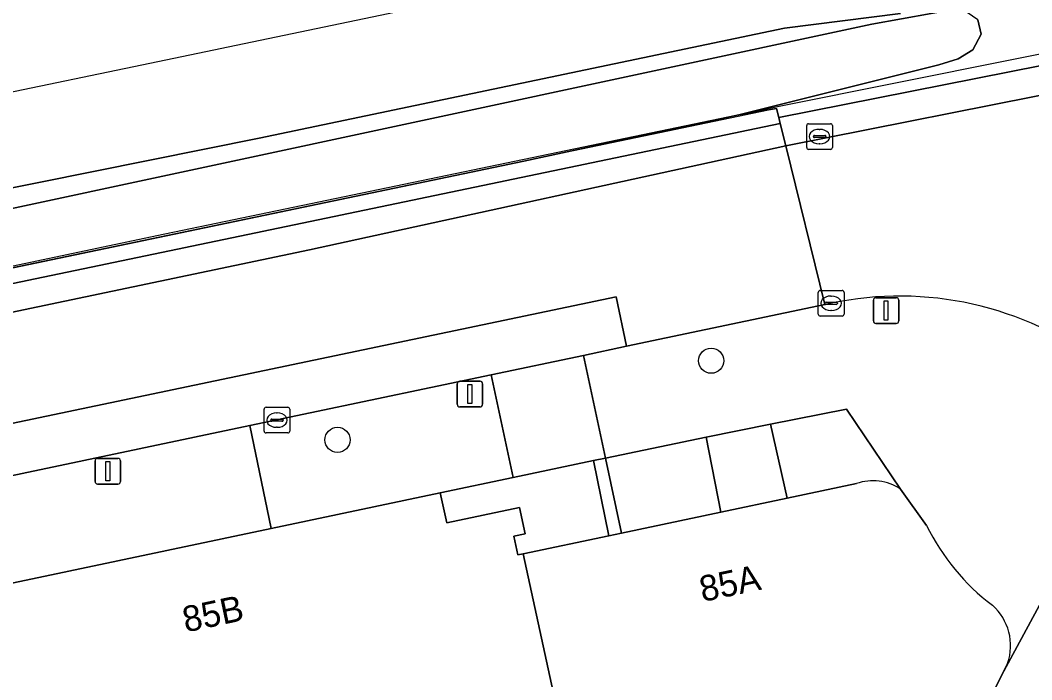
# Model space of a CAD drawing. Extents: x 162989 to 165008, y 383432 to 384338.
# Drawn here: x 163801.29 to 163840.69, y 384103.71 to 384129.41 of the extents above; entities that cross this region are included whole.
import ezdxf

# ---------------------------------------------------------------- set-up
doc = ezdxf.new("R2010")
doc.units = 0
for name, color, linetype in [('IMGEO_Boom', 7, 'Continuous'), ('IMGEO_Grasland_overig', 7, 'Continuous'), ('IMGEO_Greppel_droge_sloot', 7, 'Continuous'), ('IMGEO_Groenvoorziening', 7, 'Continuous'), ('IMGEO_Haag', 7, 'Continuous'), ('IMGEO_Hek', 7, 'Continuous'), ('IMGEO_Kolk', 7, 'Continuous'), ('IMGEO_Lichtmast', 7, 'Continuous'), ('IMGEO_Pand', 7, 'Continuous'), ('IMGEO_Pand_nummerreeks', 7, 'Continuous'), ('IMGEO_Parkeervlak_gesloten', 7, 'Continuous'), ('IMGEO_Rijbaan_lokaal_gesloten', 7, 'Continuous'), ('IMGEO_Rijbaan_lokaal_open', 7, 'Continuous'), ('IMGEO_Spoor', 7, 'Continuous'), ('IMGEO_Spoorbaan_halfverhard', 7, 'Continuous'), ('IMGEO_Voetpad_open', 7, 'Continuous')]:
    doc.layers.add(name, color=color, linetype=linetype)

msp = doc.modelspace()

# ---------------------------------------------------------------- linework, layer by layer
at = {"layer": 'IMGEO_Boom'}
for centre in [(163828.202, 384116.141), (163813.649, 384113.057)]:
    msp.add_circle(centre, 0.489, dxfattribs=at)
at = {"layer": 'IMGEO_Grasland_overig'}
for points in [[(163838.592, 384129.42), (163838.715, 384128.865), (163838.4, 384128.258), (163837.828, 384127.908), (163837.073, 384127.674), (163829.276, 384125.722), (163830.751, 384125.97), (163830.839, 384125.616), (163846.249, 384128.665), (163846.224, 384128.913), (163855.457, 384130.728)], [(163764.809, 384114.316), (163834.463, 384129.25), (163837.931, 384129.88)], [(163835.571, 384129.666), (163831.06, 384129.095), (163810.596, 384124.813), (163789.104, 384120.481)]]:
    msp.add_lwpolyline(points, dxfattribs=at)
at = {"layer": 'IMGEO_Greppel_droge_sloot'}
msp.add_lwpolyline([(163651.615, 384088.607), (163721.236, 384103.128), (163796.575, 384118.842), (163820.911, 384123.918), (163829.276, 384125.722), (163837.073, 384127.674), (163837.828, 384127.908), (163838.4, 384128.258), (163838.715, 384128.865), (163838.592, 384129.42), (163837.931, 384129.88), (163834.463, 384129.25), (163764.809, 384114.316), (163747.271, 384110.947), (163722.892, 384105.78), (163713.242, 384103.924), (163695.738, 384099.89)], dxfattribs=at)
at = {"layer": 'IMGEO_Groenvoorziening'}
for points in [[(163651.736, 384088.019), (163830.895, 384125.387), (163830.839, 384125.616), (163830.751, 384125.97), (163829.276, 384125.722), (163820.911, 384123.918), (163796.575, 384118.842), (163721.236, 384103.128), (163651.615, 384088.607)], [(163682.411, 384093.294), (163707.965, 384098.574), (163724.745, 384102.036), (163812.556, 384120.462), (163831.109, 384124.518), (163830.895, 384125.387), (163651.736, 384088.019)]]:
    msp.add_lwpolyline(points, dxfattribs=at)
at = {"layer": 'IMGEO_Haag'}
msp.add_lwpolyline([(163651.736, 384088.019), (163830.895, 384125.387), (163830.839, 384125.616), (163830.751, 384125.97), (163829.276, 384125.722), (163820.911, 384123.918), (163796.575, 384118.842), (163721.236, 384103.128), (163651.615, 384088.607)], dxfattribs=at)
at = {"layer": 'IMGEO_Hek'}
for points in [[(163774.371, 384114.211), (163806.617, 384121.018), (163830.855, 384126.062), (163844.511, 384128.802), (163854.414, 384130.95), (163855.366, 384133.259)], [(163830.751, 384125.97), (163651.615, 384088.607), (163494.89, 384056.228), (163459.651, 384049.074)]]:
    msp.add_lwpolyline(points, dxfattribs=at)
at = {"layer": 'IMGEO_Kolk'}
for p, q in [((163831.924, 384124.449), (163831.924, 384125.301)), ((163831.999, 384125.375), (163832.851, 384125.375)), ((163832.412, 384125.155), (163832.437, 384125.155)), ((163832.925, 384125.301), (163832.925, 384124.449)), ((163832.183, 384124.869), (163832.183, 384124.881)), ((163832.621, 384124.832), (163832.223, 384124.832)), ((163832.226, 384124.918), (163832.624, 384124.918)), ((163832.667, 384124.881), (163832.667, 384124.869)), ((163832.851, 384124.375), (163831.999, 384124.375)), ((163832.435, 384124.595), (163832.41, 384124.595)), ((163832.375, 384117.953), (163832.375, 384118.805)), ((163832.45, 384118.879), (163833.302, 384118.879)), ((163833.376, 384118.805), (163833.376, 384117.953)), ((163832.677, 384118.422), (163833.075, 384118.422)), ((163832.863, 384118.659), (163832.888, 384118.659)), ((163832.634, 384118.373), (163832.634, 384118.385)), ((163833.072, 384118.336), (163832.674, 384118.336)), ((163832.886, 384118.099), (163832.861, 384118.099)), ((163833.118, 384118.385), (163833.118, 384118.373)), ((163833.302, 384117.879), (163832.45, 384117.879)), ((163810.79, 384113.4), (163810.79, 384114.252)), ((163810.865, 384114.326), (163811.717, 384114.326)), ((163811.278, 384114.106), (163811.303, 384114.106)), ((163811.791, 384114.252), (163811.791, 384113.4)), ((163811.049, 384113.82), (163811.049, 384113.832)), ((163811.487, 384113.783), (163811.089, 384113.783)), ((163811.092, 384113.869), (163811.49, 384113.869)), ((163811.533, 384113.832), (163811.533, 384113.82)), ((163811.717, 384113.326), (163810.865, 384113.326)), ((163811.301, 384113.546), (163811.276, 384113.546))]:
    msp.add_line(p, q, dxfattribs=at)
for points in [[(163831.924, 384124.449), (163831.924, 384125.301)], [(163831.999, 384125.375), (163832.851, 384125.375)], [(163832.925, 384125.301), (163832.925, 384124.449)], [(163832.851, 384124.375), (163831.999, 384124.375)], [(163832.375, 384117.953), (163832.375, 384118.805)], [(163832.45, 384118.879), (163833.302, 384118.879)], [(163833.376, 384118.805), (163833.376, 384117.953)], [(163833.302, 384117.879), (163832.45, 384117.879)], [(163810.79, 384113.4), (163810.79, 384114.252)], [(163810.865, 384114.326), (163811.717, 384114.326)], [(163811.791, 384114.252), (163811.791, 384113.4)], [(163811.717, 384113.326), (163810.865, 384113.326)]]:
    msp.add_lwpolyline(points, dxfattribs=at)
for centre, radius, start, end in [((163832.001, 384125.299), 0.0765, 91.552, 178.448), ((163832.001, 384125.299), 0.0765, 91.552, 178.448), ((163832.849, 384125.299), 0.0765, 1.552, 88.448), ((163832.849, 384125.299), 0.0765, 1.552, 88.448), ((163832.223, 384124.878), 0.0403, 85.8775, 175.7526), ((163832.22, 384124.868), 0.0366, 178.938, 274.7102), ((163832.624, 384124.875), 0.043, 264.8664, 352.4533), ((163832.628, 384124.88), 0.0386, 1.7309, 96.639), ((163832.001, 384124.451), 0.0765, 181.552, 268.448), ((163832.001, 384124.451), 0.0765, 181.552, 268.448), ((163832.849, 384124.451), 0.0765, 271.552, 358.448), ((163832.849, 384124.451), 0.0765, 271.552, 358.448), ((163832.452, 384118.803), 0.0765, 91.552, 178.448), ((163832.452, 384118.803), 0.0765, 91.552, 178.448), ((163833.3, 384118.803), 0.0765, 1.552, 88.448), ((163833.3, 384118.803), 0.0765, 1.552, 88.448), ((163832.674, 384118.382), 0.0403, 85.8775, 175.7526), ((163833.079, 384118.384), 0.0386, 1.7309, 96.639), ((163832.671, 384118.372), 0.0366, 178.938, 274.7102), ((163833.075, 384118.379), 0.043, 264.8664, 352.4533), ((163832.452, 384117.955), 0.0765, 181.552, 268.448), ((163832.452, 384117.955), 0.0765, 181.552, 268.448), ((163833.3, 384117.955), 0.0765, 271.552, 358.448), ((163833.3, 384117.955), 0.0765, 271.552, 358.448), ((163810.867, 384114.25), 0.0765, 91.552, 178.448), ((163810.867, 384114.25), 0.0765, 91.552, 178.448), ((163811.715, 384114.25), 0.0765, 1.552, 88.448), ((163811.715, 384114.25), 0.0765, 1.552, 88.448), ((163811.089, 384113.829), 0.0403, 85.8775, 175.7526), ((163811.086, 384113.819), 0.0366, 178.938, 274.7102), ((163811.49, 384113.826), 0.043, 264.8664, 352.4533), ((163811.494, 384113.831), 0.0386, 1.7309, 96.639), ((163810.867, 384113.402), 0.0765, 181.552, 268.448), ((163810.867, 384113.402), 0.0765, 181.552, 268.448), ((163811.715, 384113.402), 0.0765, 271.552, 358.448), ((163811.715, 384113.402), 0.0765, 271.552, 358.448)]:
    msp.add_arc(centre, radius, start, end, dxfattribs=at)
for centre, major_axis, ratio, start_param, end_param in [((163832.411, 384124.875), (-0.387, 0.002), 0.722429, 4.712389, 7.853982), ((163832.436, 384124.875), (-0.39, 0.002), 0.717154, 1.570796, 4.712389), ((163832.862, 384118.379), (-0.387, 0.002), 0.722429, 4.712389, 7.853982), ((163832.887, 384118.379), (-0.39, 0.002), 0.717154, 1.570796, 4.712389), ((163811.277, 384113.826), (-0.387, 0.002), 0.722429, 4.712389, 7.853982), ((163811.302, 384113.826), (-0.39, 0.002), 0.717154, 1.570796, 4.712389)]:
    msp.add_ellipse(centre, major_axis=major_axis, ratio=ratio, start_param=start_param, end_param=end_param, dxfattribs=at)
at = {"layer": 'IMGEO_Lichtmast'}
for p, q in [((163834.519, 384117.694), (163834.519, 384118.494)), ((163834.519, 384118.494), (163834.519, 384117.694)), ((163834.619, 384118.594), (163835.409, 384118.594)), ((163835.409, 384118.594), (163834.619, 384118.594)), ((163835.509, 384118.494), (163835.509, 384117.694)), ((163835.509, 384117.694), (163835.509, 384118.494)), ((163835.409, 384117.594), (163834.619, 384117.594)), ((163834.619, 384117.594), (163835.409, 384117.594)), ((163818.409, 384115.343), (163819.199, 384115.343)), ((163819.199, 384115.343), (163818.409, 384115.343)), ((163818.309, 384114.443), (163818.309, 384115.243)), ((163818.309, 384115.243), (163818.309, 384114.443)), ((163819.299, 384115.243), (163819.299, 384114.443)), ((163819.299, 384114.443), (163819.299, 384115.243)), ((163819.199, 384114.343), (163818.409, 384114.343)), ((163818.409, 384114.343), (163819.199, 384114.343)), ((163804.206, 384111.436), (163804.206, 384112.236)), ((163804.206, 384112.236), (163804.206, 384111.436)), ((163804.306, 384112.336), (163805.096, 384112.336)), ((163805.096, 384112.336), (163804.306, 384112.336)), ((163805.196, 384112.236), (163805.196, 384111.436)), ((163805.196, 384111.436), (163805.196, 384112.236)), ((163805.096, 384111.336), (163804.306, 384111.336)), ((163804.306, 384111.336), (163805.096, 384111.336))]:
    msp.add_line(p, q, dxfattribs=at)
for points in [[(163834.939, 384118.469), (163835.089, 384118.469), (163835.089, 384117.719), (163834.939, 384117.719), (163834.939, 384118.469)], [(163818.729, 384115.218), (163818.879, 384115.218), (163818.879, 384114.468), (163818.729, 384114.468), (163818.729, 384115.218)], [(163804.626, 384112.211), (163804.776, 384112.211), (163804.776, 384111.461), (163804.626, 384111.461), (163804.626, 384112.211)]]:
    msp.add_lwpolyline(points, dxfattribs=at)
for centre, start, end in [((163834.619, 384118.494), 90, 180), ((163834.619, 384118.494), 90, 180), ((163835.409, 384118.494), 0, 90), ((163835.409, 384118.494), 360, 90), ((163834.619, 384117.694), 180, 270), ((163834.619, 384117.694), 180, 270), ((163835.409, 384117.694), 270, 0), ((163835.409, 384117.694), 270, 0), ((163818.409, 384115.243), 90, 180), ((163818.409, 384115.243), 90, 180), ((163819.199, 384115.243), 0, 90), ((163819.199, 384115.243), 360, 90), ((163818.409, 384114.443), 180, 270), ((163818.409, 384114.443), 180, 270), ((163819.199, 384114.443), 270, 0), ((163819.199, 384114.443), 270, 0), ((163804.306, 384112.236), 90, 180), ((163804.306, 384112.236), 90, 180), ((163805.096, 384112.236), 0, 90), ((163805.096, 384112.236), 360, 90), ((163804.306, 384111.436), 180, 270), ((163804.306, 384111.436), 180, 270), ((163805.096, 384111.436), 270, 0), ((163805.096, 384111.436), 270, 0)]:
    msp.add_arc(centre, 0.1, start, end, dxfattribs=at)
at = {"layer": 'IMGEO_Pand'}
for points in [[(163833.86, 384111.356), (163831.165, 384110.787), (163828.576, 384110.241), (163824.715, 384109.426), (163824.217, 384109.321), (163820.882, 384108.618), (163822.303, 384102.048), (163825.009, 384102.633), (163826.1, 384099.713), (163824.042, 384095.656), (163833.039, 384091.042), (163839.604, 384104.048), (163839.75, 384104.35)], [(163836.595, 384109.724), (163835.577, 384111.142)]]:
    msp.add_lwpolyline(points, dxfattribs=at)
msp.add_lwpolyline([(163820.882, 384108.618), (163820.671, 384108.573), (163820.516, 384109.306), (163820.956, 384109.398), (163820.739, 384110.425), (163817.901, 384109.826), (163817.653, 384111), (163811.068, 384109.609), (163799.112, 384107.083), (163799.731, 384104.15), (163796.06, 384103.375), (163799.533, 384093.442), (163800.928, 384094.147), (163807.681, 384097.564), (163808.03, 384097.74), (163807.498, 384098.845), (163813.189, 384100.076), (163822.303, 384102.048)], close=True, dxfattribs=at)
for centre, radius, start, end in [((163834.5, 384109.496), 1.967, 56.7989, 108.9921), ((163844.377, 384113.526), 8.662, 206.0402, 232.9447), ((163837.751, 384105.037), 2.114, 341.0423, 48.2654)]:
    msp.add_arc(centre, radius, start, end, dxfattribs=at)
at = {"layer": 'IMGEO_Parkeervlak_gesloten'}
msp.add_lwpolyline([(163776.585, 384106.531), (163785.469, 384108.401), (163794.883, 384110.382), (163810.228, 384113.612), (163819.633, 384115.592), (163823.232, 384116.349), (163824.909, 384116.702), (163824.503, 384118.628), (163797.649, 384113.01), (163765.036, 384106.198), (163765.448, 384104.188)], close=True, dxfattribs=at)
at = {"layer": 'IMGEO_Rijbaan_lokaal_gesloten'}
msp.add_lwpolyline([(163824.909, 384116.702), (163832.633, 384118.328), (163831.109, 384124.518), (163812.556, 384120.462), (163724.745, 384102.036), (163725.942, 384095.873), (163732.071, 384097.163), (163731.698, 384099.159), (163759.14, 384104.898), (163759.551, 384102.946), (163760.82, 384103.213), (163764.526, 384103.994), (163765.448, 384104.188), (163765.036, 384106.198), (163797.649, 384113.01), (163824.503, 384118.628)], close=True, dxfattribs=at)
at = {"layer": 'IMGEO_Rijbaan_lokaal_open'}
msp.add_lwpolyline([(163843.931, 384124.881), (163842.766, 384124.652), (163842.704, 384124.996), (163842.369, 384126.742), (163831.109, 384124.518), (163832.633, 384118.328), (163832.876, 384118.379)], dxfattribs=at)
msp.add_arc((163835.552, 384105.706), 12.953, 52.8144, 101.9248, dxfattribs=at)
at = {"layer": 'IMGEO_Spoor'}
msp.add_lwpolyline([(164789.572, 384332.389), (164775.58, 384329.429), (164644.744, 384302.256), (164570.629, 384286.722), (164345.336, 384239.894), (164220.116, 384213.747), (164092.662, 384187.275), (164071.527, 384182.957), (163942.979, 384156.119), (163900.983, 384147.477), (163806.025, 384127.659), (163575.669, 384079.775)], dxfattribs=at)
at = {"layer": 'IMGEO_Spoorbaan_halfverhard'}
msp.add_lwpolyline([(163789.104, 384120.481), (163810.596, 384124.813), (163831.06, 384129.095), (163835.571, 384129.666)], dxfattribs=at)
at = {"layer": 'IMGEO_Voetpad_open'}
for points in [[(163854.475, 384129.198), (163855.457, 384130.728), (163846.224, 384128.913), (163846.249, 384128.665), (163830.839, 384125.616), (163830.895, 384125.387), (163831.109, 384124.518), (163842.369, 384126.742), (163842.527, 384126.773), (163848.264, 384127.906)], [(163824.089, 384112.349), (163823.232, 384116.349), (163819.633, 384115.592), (163820.489, 384111.596), (163823.615, 384112.253)], [(163817.653, 384111), (163820.489, 384111.596), (163819.633, 384115.592), (163810.228, 384113.612), (163811.068, 384109.609)], [(163811.068, 384109.609), (163810.228, 384113.612), (163794.883, 384110.382), (163796.27, 384106.482), (163799.112, 384107.083)], [(163828.003, 384113.169), (163828.576, 384110.241), (163831.165, 384110.787), (163830.517, 384113.663)], [(163824.089, 384112.349), (163824.715, 384109.426), (163828.576, 384110.241), (163828.003, 384113.169)], [(163820.489, 384111.596), (163817.653, 384111), (163817.901, 384109.826), (163820.739, 384110.425), (163820.956, 384109.398), (163820.516, 384109.306), (163820.671, 384108.573), (163820.882, 384108.618), (163824.217, 384109.321), (163823.615, 384112.253)], [(163823.615, 384112.253), (163824.217, 384109.321), (163824.715, 384109.426), (163824.089, 384112.349)]]:
    msp.add_lwpolyline(points, close=True, dxfattribs=at)
for points in [[(163832.876, 384118.379), (163832.633, 384118.328), (163824.909, 384116.702), (163823.232, 384116.349), (163824.089, 384112.349), (163828.003, 384113.169), (163830.517, 384113.663), (163833.471, 384114.251), (163835.577, 384111.142), (163836.595, 384109.724)], [(163845.14, 384114.307), (163839.604, 384104.048), (163833.039, 384091.042), (163827.304, 384079.681), (163823.683, 384072.507), (163822.343, 384069.959), (163821.36, 384068.226), (163821.507, 384068.122), (163824.405, 384066.034), (163819.835, 384058.771), (163818.285, 384059.918), (163817.775, 384059.146), (163810.967, 384045.208), (163810.741, 384045.3), (163809.212, 384042.588), (163809.104, 384042.631), (163804.861, 384033.884), (163796.988, 384017.276), (163789.265, 384000), (163788.336, 383997.923), (163787.048, 383994.75)], [(163835.577, 384111.142), (163833.471, 384114.251), (163830.517, 384113.663), (163831.165, 384110.787), (163833.86, 384111.356)], [(163839.75, 384104.35), (163839.604, 384104.048), (163845.14, 384114.307)]]:
    msp.add_lwpolyline(points, dxfattribs=at)
for centre, radius, start, end in [((163835.552, 384105.706), 12.953, 52.8144, 101.9248), ((163834.5, 384109.496), 1.967, 56.7989, 108.9921), ((163844.377, 384113.526), 8.662, 206.0402, 232.9447), ((163837.751, 384105.037), 2.114, 341.0423, 48.2654)]:
    msp.add_arc(centre, radius, start, end, dxfattribs=at)

# ---------------------------------------------------------------- texts
at = {"layer": 'IMGEO_Pand_nummerreeks'}
for s, rotation, p in [('85A', 11.9144, (163827.867, 384106.739)), ('85B', 11.929, (163807.733, 384105.552))]:
    msp.add_text(s, height=1, rotation=rotation, dxfattribs=at).set_placement(p)

doc.saveas('drawing.dxf')
